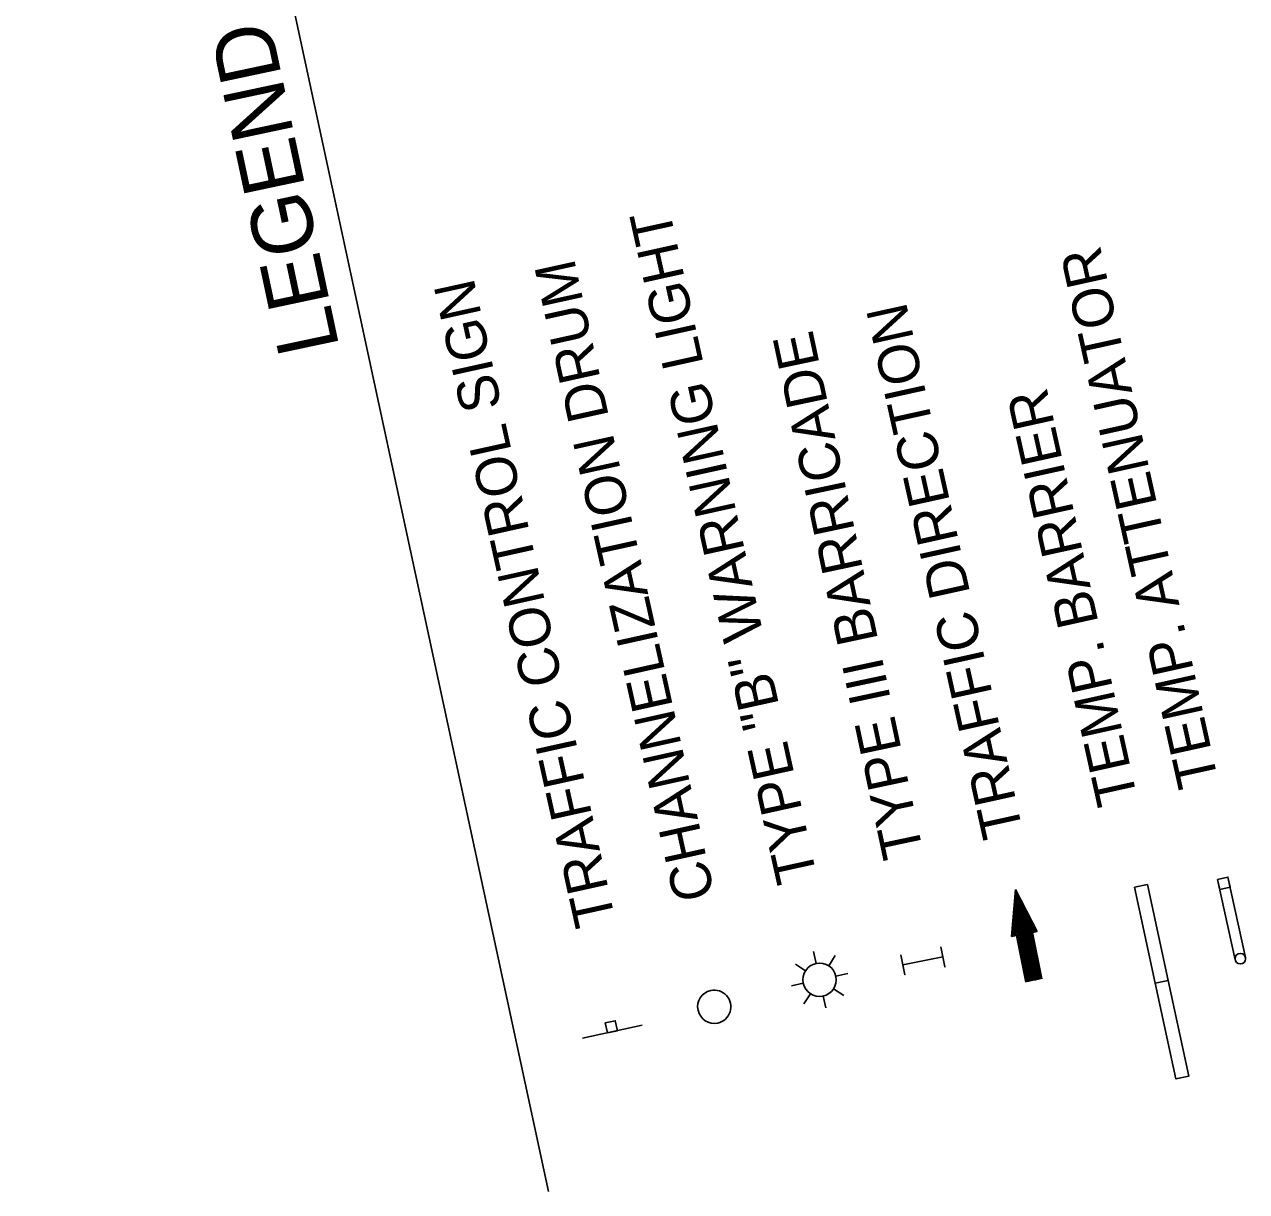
# Model space of a CAD drawing. Extents: x 1795987 to 1799689, y 243690 to 251545.
# Drawn here: x 1799455.4 to 1799689.1, y 250274.2 to 250497.4 of the extents above; entities that cross this region are included whole.
import ezdxf

# ---------------------------------------------------------------- set-up
doc = ezdxf.new("R2010")
doc.units = 0
doc.layers.add('LEGEND', color=7, linetype='Continuous')
doc.layers.add('Level 2', color=7, linetype='Continuous')

# ---------------------------------------------------------------- blocks, each defined once
blk = doc.blocks.new('T21LR')
at = {"layer": 'Level 2'}
for p, q in [((0, 2), (31.5, 2)), ((0, -2), (31.5, -2))]:
    blk.add_line(p, q, dxfattribs=at)
blk.add_lwpolyline([(0, -2), (4, -2), (4, 2), (0, 2)], close=True, dxfattribs=at)
blk.add_circle((31.5, 0), 2, dxfattribs=at)

msp = doc.modelspace()

# ---------------------------------------------------------------- linework, layer by layer
at = {"layer": 'LEGEND'}
for p, q in [((1799555.62, 250274.21), (1799455.36, 250739.61)), ((1799644.94, 250331.95), (1799644.19, 250322.98)), ((1799649.1, 250323.97), (1799644.94, 250331.95)), ((1799644.19, 250322.98), (1799645.12, 250323.16)), ((1799645.12, 250323.16), (1799646.91, 250314.26)), ((1799648.18, 250323.78), (1799649.1, 250323.97)), ((1799649.97, 250314.88), (1799648.18, 250323.78)), ((1799606.79, 250317.84), (1799606.3, 250320.1)), ((1799610.45, 250319.34), (1799609.19, 250317.4)), ((1799604.78, 250316.45), (1799602.83, 250317.7)), ((1799604.34, 250314.05), (1799602.08, 250313.56)), ((1799610.58, 250315.39), (1799612.84, 250315.88)), ((1799604.47, 250310.09), (1799605.73, 250312.03)), ((1799608.13, 250311.6), (1799608.62, 250309.34)), ((1799612.09, 250311.73), (1799610.14, 250312.99)), ((1799573.54, 250306), (1799562.1, 250303.53))]:
    msp.add_line(p, q, dxfattribs=at)
for points in [[(1799670.15, 250332.93), (1799667.71, 250332.4), (1799671.66, 250314.07), (1799674.1, 250314.6)], [(1799674.1, 250314.6), (1799671.66, 250314.07), (1799675.61, 250295.75), (1799678.05, 250296.27)], [(1799566.87, 250304.56), (1799566.46, 250306.46), (1799568.36, 250306.88), (1799568.77, 250304.97)]]:
    msp.add_lwpolyline(points, close=True, dxfattribs=at)
for points in [[(1799644.83, 250330.67), (1799648.09, 250314.5)], [(1799644.91, 250331.6), (1799648.35, 250314.55)], [(1799645.21, 250331.43), (1799648.6, 250314.6)], [(1799645.64, 250330.6), (1799648.86, 250314.65)], [(1799644.6, 250327.87), (1799647.33, 250314.34)], [(1799644.68, 250328.81), (1799647.58, 250314.4)], [(1799644.75, 250329.74), (1799647.84, 250314.45)], [(1799646.07, 250329.77), (1799649.11, 250314.7)], [(1799646.5, 250328.94), (1799649.37, 250314.75)], [(1799646.94, 250328.11), (1799649.62, 250314.81)], [(1799644.44, 250326.01), (1799645.02, 250323.14)], [(1799644.52, 250326.94), (1799647.07, 250314.29)], [(1799647.37, 250327.28), (1799649.88, 250314.86)], [(1799647.8, 250326.45), (1799648.34, 250323.81)], [(1799648.24, 250325.63), (1799648.59, 250323.86)], [(1799644.21, 250323.21), (1799644.26, 250322.99)], [(1799644.29, 250324.14), (1799644.51, 250323.04)], [(1799644.37, 250325.08), (1799644.77, 250323.09)], [(1799648.67, 250324.8), (1799648.85, 250323.91)], [(1799630.67, 250321), (1799631.43, 250317.18), (1799631.05, 250319.09), (1799623.4, 250317.57), (1799623.78, 250315.66), (1799623.02, 250319.49)]]:
    msp.add_lwpolyline(points, dxfattribs=at)
msp.add_circle((1799607.46, 250314.72), 3.19, dxfattribs=at)
for start, end in [(102.1577, 282.1577), (282.1577, 102.1577)]:
    msp.add_arc((1799587.31, 250309.55), 3.18, start, end, dxfattribs=at)

# ---------------------------------------------------------------- block references
at = {"layer": 'LEGEND', "xscale": 0.5000000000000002, "yscale": 0.5000000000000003, "rotation": -77.69303510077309}
msp.add_blockref('T21LR', (1799684.57, 250334.13), dxfattribs=at)

# ---------------------------------------------------------------- texts
at = {"layer": 'LEGEND'}
for s, height, rotation, p in [('LEGEND', 11.7, 101.9916, (1799515.63, 250435.66)), ('TYPE "B" WARNING LIGHT', 7.7999, 102.4707, (1799607.04, 250334.14)), ('TEMP. ATTENUATOR', 7.7999, 102.4707, (1799683.81, 250352.4)), ('CHANNELIZATION DRUM', 7.7999, 102.4707, (1799587.46, 250330.69)), ('TRAFFIC CONTROL SIGN', 7.7999, 102.4707, (1799568.48, 250325.84)), ('TRAFFIC DIRECTION', 7.7999, 102.4707, (1799646.43, 250342.77)), ('TYPE III BARRICADE', 7.7999, 101.9916, (1799627.36, 250338.82)), ('TEMP. BARRIER', 7.7999, 102.4707, (1799668.34, 250349.01))]:
    msp.add_text(s, height=height, rotation=rotation, dxfattribs=at).set_placement(p)

doc.saveas('drawing.dxf')
